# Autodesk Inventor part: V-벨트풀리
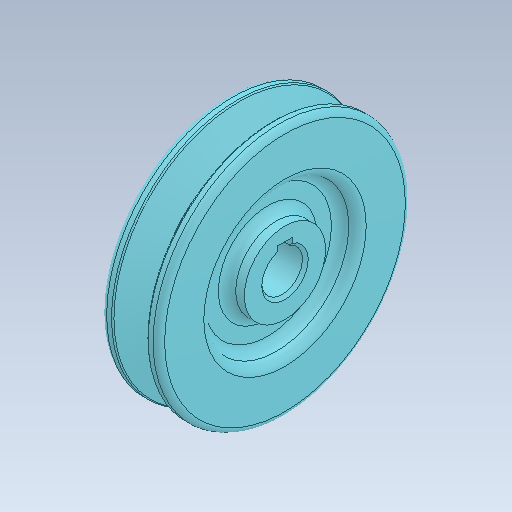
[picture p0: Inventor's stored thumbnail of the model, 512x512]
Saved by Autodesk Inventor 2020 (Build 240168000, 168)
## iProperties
Created: 2024-04
Part Number: V-벨트풀리
Material: 일반
Document SubType Name: Modeling
Designer: oem
Density: 1 g/cm^3
Appearance: 기본값
Mass: 74.8308 g
Surface Area: 229.616 cm^2
Volume: 74.8308 cm^3
Sending System: Autodesk Inventor 2025
Preprocessor: ST-DEVELOPER v20
Author: jhkim
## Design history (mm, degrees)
feature "솔리드1"
node "솔리드2"
